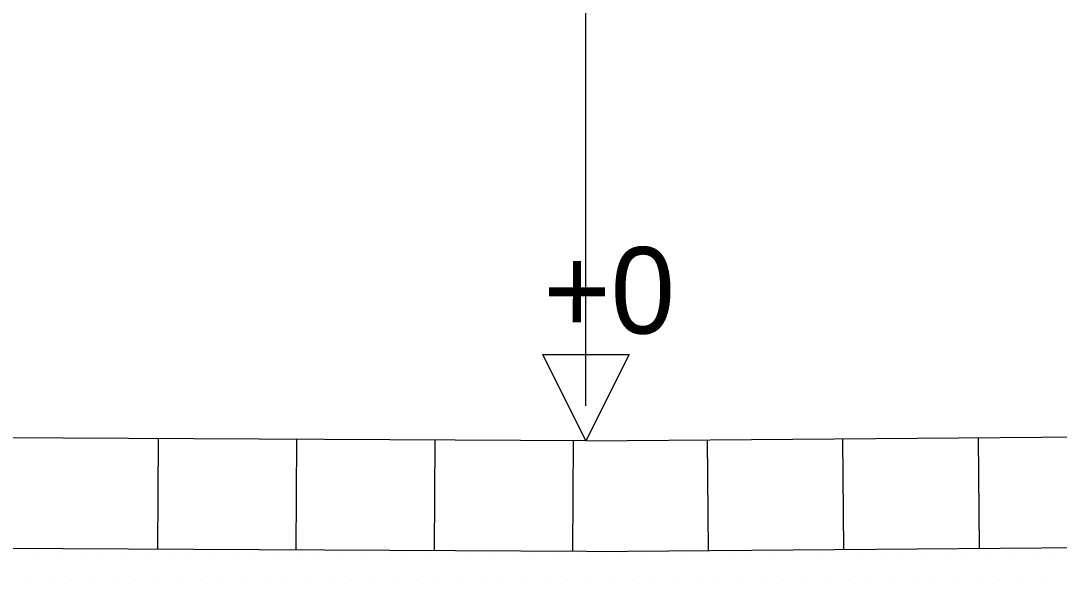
# Model space of a CAD drawing. Extents: x -219625893 to 7498339, y 5791790 to 5792761.
# Drawn here: x 7495290.28 to 7495305.31, y 5791870.69 to 5791878.77 of the extents above; entities that cross this region are included whole.
import ezdxf

# ---------------------------------------------------------------- set-up
doc = ezdxf.new("R2010")
doc.units = 0
for name, color, linetype in [('D_kons_wyp_podsypka_cem-piask', 7, 'Continuous'), ('D_wymiary_500', 7, 'Continuous'), ('Level 1', 7, 'Continuous'), ('Level 10', 7, 'Continuous'), ('wymiary', 7, 'Continuous')]:
    doc.layers.add(name, color=color, linetype=linetype)

msp = doc.modelspace()

# ---------------------------------------------------------------- linework, layer by layer
at = {"layer": 'D_kons_wyp_podsypka_cem-piask'}
for p, q in [((7495290.539, 5791871.005), (7495290.539, 5791871.005)), ((7495290.852, 5791871.005), (7495290.852, 5791871.005)), ((7495291.164, 5791871.005), (7495291.164, 5791871.005)), ((7495291.477, 5791871.005), (7495291.477, 5791871.005)), ((7495291.789, 5791871.005), (7495291.789, 5791871.005)), ((7495292.102, 5791871.005), (7495292.102, 5791871.005)), ((7495292.414, 5791871.005), (7495292.414, 5791871.005)), ((7495292.727, 5791871.005), (7495292.727, 5791871.005)), ((7495293.039, 5791871.005), (7495293.039, 5791871.005)), ((7495293.352, 5791871.005), (7495293.352, 5791871.005)), ((7495293.664, 5791871.005), (7495293.664, 5791871.005)), ((7495293.977, 5791871.005), (7495293.977, 5791871.005)), ((7495294.289, 5791871.005), (7495294.289, 5791871.005)), ((7495294.602, 5791871.005), (7495294.602, 5791871.005)), ((7495294.914, 5791871.005), (7495294.914, 5791871.005)), ((7495295.227, 5791871.005), (7495295.227, 5791871.005)), ((7495295.539, 5791871.005), (7495295.539, 5791871.005)), ((7495295.852, 5791871.005), (7495295.852, 5791871.005)), ((7495296.164, 5791871.005), (7495296.164, 5791871.005)), ((7495296.477, 5791871.005), (7495296.477, 5791871.005)), ((7495296.789, 5791871.005), (7495296.789, 5791871.005)), ((7495297.102, 5791871.005), (7495297.102, 5791871.005)), ((7495297.414, 5791871.005), (7495297.414, 5791871.005)), ((7495297.727, 5791871.005), (7495297.727, 5791871.005)), ((7495298.039, 5791871.005), (7495298.039, 5791871.005)), ((7495298.352, 5791871.005), (7495298.352, 5791871.005)), ((7495298.664, 5791871.005), (7495298.664, 5791871.005)), ((7495298.977, 5791871.005), (7495298.977, 5791871.005)), ((7495299.289, 5791871.005), (7495299.289, 5791871.005)), ((7495299.602, 5791871.005), (7495299.602, 5791871.005)), ((7495299.914, 5791871.005), (7495299.914, 5791871.005)), ((7495300.227, 5791871.005), (7495300.227, 5791871.005)), ((7495300.539, 5791871.005), (7495300.539, 5791871.005)), ((7495300.852, 5791871.005), (7495300.852, 5791871.005)), ((7495301.164, 5791871.005), (7495301.164, 5791871.005)), ((7495301.477, 5791871.005), (7495301.477, 5791871.005)), ((7495301.789, 5791871.005), (7495301.789, 5791871.005)), ((7495302.102, 5791871.005), (7495302.102, 5791871.005)), ((7495302.414, 5791871.005), (7495302.414, 5791871.005)), ((7495302.727, 5791871.005), (7495302.727, 5791871.005)), ((7495303.039, 5791871.005), (7495303.039, 5791871.005)), ((7495303.352, 5791871.005), (7495303.352, 5791871.005)), ((7495303.664, 5791871.005), (7495303.664, 5791871.005)), ((7495303.977, 5791871.005), (7495303.977, 5791871.005)), ((7495304.289, 5791871.005), (7495304.289, 5791871.005)), ((7495304.602, 5791871.005), (7495304.602, 5791871.005)), ((7495304.914, 5791871.005), (7495304.914, 5791871.005)), ((7495305.227, 5791871.005), (7495305.227, 5791871.005)), ((7495290.383, 5791870.693), (7495290.383, 5791870.693)), ((7495290.695, 5791870.693), (7495290.695, 5791870.693)), ((7495291.008, 5791870.693), (7495291.008, 5791870.693)), ((7495291.32, 5791870.693), (7495291.32, 5791870.693)), ((7495291.633, 5791870.693), (7495291.633, 5791870.693)), ((7495291.945, 5791870.693), (7495291.945, 5791870.693)), ((7495292.258, 5791870.693), (7495292.258, 5791870.693)), ((7495292.57, 5791870.693), (7495292.57, 5791870.693)), ((7495292.883, 5791870.693), (7495292.883, 5791870.693)), ((7495293.195, 5791870.693), (7495293.195, 5791870.693)), ((7495293.508, 5791870.693), (7495293.508, 5791870.693)), ((7495293.82, 5791870.693), (7495293.82, 5791870.693)), ((7495294.133, 5791870.693), (7495294.133, 5791870.693)), ((7495294.445, 5791870.693), (7495294.445, 5791870.693)), ((7495294.758, 5791870.693), (7495294.758, 5791870.693)), ((7495295.07, 5791870.693), (7495295.07, 5791870.693)), ((7495295.383, 5791870.693), (7495295.383, 5791870.693)), ((7495295.695, 5791870.693), (7495295.695, 5791870.693)), ((7495296.008, 5791870.693), (7495296.008, 5791870.693)), ((7495296.32, 5791870.693), (7495296.32, 5791870.693)), ((7495296.633, 5791870.693), (7495296.633, 5791870.693)), ((7495296.945, 5791870.693), (7495296.945, 5791870.693)), ((7495297.258, 5791870.693), (7495297.258, 5791870.693)), ((7495297.57, 5791870.693), (7495297.57, 5791870.693)), ((7495297.883, 5791870.693), (7495297.883, 5791870.693)), ((7495298.195, 5791870.693), (7495298.195, 5791870.693)), ((7495298.508, 5791870.693), (7495298.508, 5791870.693)), ((7495298.82, 5791870.693), (7495298.82, 5791870.693)), ((7495299.133, 5791870.693), (7495299.133, 5791870.693)), ((7495299.445, 5791870.693), (7495299.445, 5791870.693)), ((7495299.758, 5791870.693), (7495299.758, 5791870.693)), ((7495300.07, 5791870.693), (7495300.07, 5791870.693)), ((7495300.383, 5791870.693), (7495300.383, 5791870.693)), ((7495300.695, 5791870.693), (7495300.695, 5791870.693)), ((7495301.008, 5791870.693), (7495301.008, 5791870.693)), ((7495301.32, 5791870.693), (7495301.32, 5791870.693)), ((7495301.633, 5791870.693), (7495301.633, 5791870.693)), ((7495301.945, 5791870.693), (7495301.945, 5791870.693)), ((7495302.258, 5791870.693), (7495302.258, 5791870.693)), ((7495302.57, 5791870.693), (7495302.57, 5791870.693)), ((7495302.883, 5791870.693), (7495302.883, 5791870.693)), ((7495303.195, 5791870.693), (7495303.195, 5791870.693)), ((7495303.508, 5791870.693), (7495303.508, 5791870.693)), ((7495303.82, 5791870.693), (7495303.82, 5791870.693)), ((7495304.133, 5791870.693), (7495304.133, 5791870.693)), ((7495304.445, 5791870.693), (7495304.445, 5791870.693)), ((7495304.758, 5791870.693), (7495304.758, 5791870.693)), ((7495305.07, 5791870.693), (7495305.07, 5791870.693))]:
    msp.add_line(p, q, dxfattribs=at)
at = {"layer": 'D_wymiary_500'}
msp.add_line((7495298.458, 5791873.199), (7495298.458, 5791889.967), dxfattribs=at)
at = {"layer": 'Level 1'}
for p, q in [((7495298.458, 5791872.694), (7495297.834, 5791873.945)), ((7495297.834, 5791873.945), (7495299.084, 5791873.944)), ((7495299.084, 5791873.944), (7495298.458, 5791872.694))]:
    msp.add_line(p, q, dxfattribs=at)
at = {"layer": 'Level 10'}
for p, q in [((7495298.458, 5791872.694), (7495361.458, 5791873.199)), ((7495298.458, 5791872.694), (7495250.391, 5791872.935)), ((7495292.265, 5791871.125), (7495292.273, 5791872.725)), ((7495294.267, 5791871.115), (7495294.275, 5791872.715)), ((7495296.269, 5791871.105), (7495296.277, 5791872.705)), ((7495298.271, 5791871.093), (7495298.279, 5791872.695)), ((7495300.231, 5791871.109), (7495300.218, 5791872.709)), ((7495302.191, 5791871.124), (7495302.178, 5791872.724)), ((7495304.151, 5791871.14), (7495304.138, 5791872.74)), ((7495298.461, 5791871.094), (7495361.471, 5791871.6)), ((7495298.461, 5791871.094), (7495250.391, 5791871.335))]:
    msp.add_line(p, q, dxfattribs=at)

# ---------------------------------------------------------------- texts
at = {"layer": 'wymiary'}
msp.add_text('+0', height=1.25, rotation=359.9571, dxfattribs=at).set_placement((7495297.841, 5791874.248))

doc.saveas('drawing.dxf')
